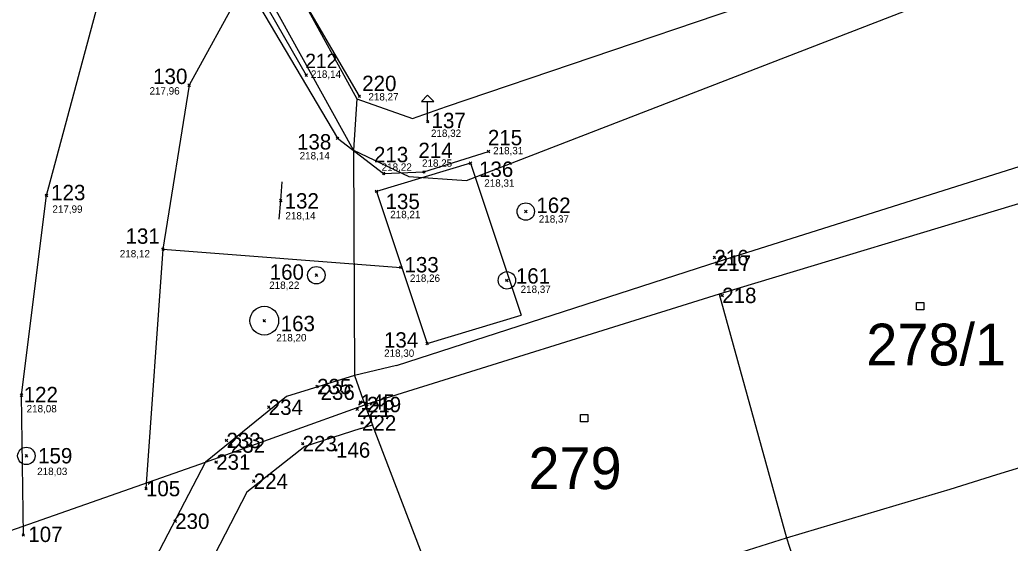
# Model space of a CAD drawing. Extents: x -711879 to -711361, y -1048782 to -1048177.
# Drawn here: x -711645.48 to -711605.14, y -1048546.23 to -1048524.94 of the extents above; entities that cross this region are included whole.
import ezdxf

# ---------------------------------------------------------------- set-up
doc = ezdxf.new("R2010")
doc.units = 0
for name, color, linetype in [('body', 7, 'Continuous'), ('kresba', 7, 'Continuous'), ('Vrstva 1', 7, 'Continuous'), ('Vrstva 15', 7, 'Continuous'), ('Vrstva 2', 7, 'Continuous'), ('Vrstva 20', 7, 'Continuous'), ('Vrstva 25', 7, 'Continuous'), ('Vrstva 41', 7, 'Continuous'), ('Vrstva 46', 7, 'Continuous'), ('výšky', 7, 'Continuous')]:
    doc.layers.add(name, color=color, linetype=linetype)

msp = doc.modelspace()

# ---------------------------------------------------------------- linework, layer by layer
at = {"layer": 'kresba'}
for p, q in [((-711636.56, -1048519.64), (-711631.65, -1048528.05)), ((-711636.32, -1048522.849), (-711633.81, -1048527.19)), ((-711636.56, -1048522.97), (-711632.54, -1048529.76)), ((-711627.12, -1048530.77), (-711630.95, -1048531.92)), ((-711627.12, -1048530.77), (-711625.06, -1048536.96)), ((-711634.85, -1048532.29), (-711634.79, -1048531.53)), ((-711630.95, -1048531.92), (-711628.89, -1048538.11)), ((-711634.91, -1048533.05), (-711634.85, -1048532.29)), ((-711639.65, -1048534.27), (-711640.34, -1048544.01)), ((-711639.65, -1048534.27), (-711629.96, -1048535.01)), ((-711628.89, -1048538.11), (-711625.06, -1048536.96))]:
    msp.add_line(p, q, dxfattribs=at)
for points in [[(-711645.33, -1048545.9), (-711645.41, -1048540.21), (-711644.39, -1048532.08), (-711642.22, -1048524), (-711639.471, -1048515.651)], [(-711636.47, -1048523.76), (-711638.58, -1048527.6), (-711639.65, -1048534.27)], [(-711628.87, -1048529.08), (-711628.87, -1048528.26), (-711628.62, -1048528.26), (-711628.87, -1048528.01), (-711629.12, -1048528.26), (-711628.87, -1048528.26)], [(-711632.54, -1048529.76), (-711630.66, -1048531.19), (-711629.02, -1048531.13), (-711626.39, -1048530.29)]]:
    msp.add_lwpolyline(points, dxfattribs=at)
for centre, radius in [((-711624.87, -1048532.74), 0.355), ((-711633.4, -1048535.33), 0.355), ((-711625.64, -1048535.54), 0.355), ((-711635.52, -1048537.18), 0.585), ((-711645.21, -1048542.68), 0.355)]:
    msp.add_circle(centre, radius, dxfattribs=at)
at = {"layer": 'Vrstva 1'}
for p, q in [((-711636.32, -1048519.83), (-711631.75, -1048528.15)), ((-711628.1, -1048528.47), (-711616.23, -1048524.45)), ((-711631.75, -1048528.15), (-711631.89, -1048530.24)), ((-711631.75, -1048528.15), (-711629.48, -1048528.95)), ((-711629.48, -1048528.95), (-711628.1, -1048528.47)), ((-711631.89, -1048530.24), (-711631.85, -1048539.41)), ((-711603.68, -1048532.09), (-711617, -1048536.1)), ((-711617, -1048536.1), (-711631.42, -1048540.6)), ((-711617, -1048536.1), (-711614.25, -1048546.01)), ((-711631.85, -1048539.41), (-711631.42, -1048540.6)), ((-711637.91, -1048542.94), (-711631.42, -1048540.6)), ((-711631.42, -1048540.6), (-711631.11, -1048541.42)), ((-711631.59, -1048541.57), (-711631.11, -1048541.42)), ((-711627.66, -1048550.43), (-711631.11, -1048541.42)), ((-711631.59, -1048541.57), (-711633.87, -1048542.3)), ((-711633.87, -1048542.3), (-711636.23, -1048544.16)), ((-711654.39, -1048548.7), (-711637.91, -1048542.94)), ((-711640.49, -1048547.86), (-711637.91, -1048542.94)), ((-711636.23, -1048544.16), (-711638.53, -1048548.61)), ((-711614.25, -1048546.01), (-711612.88, -1048550.24))]:
    msp.add_line(p, q, dxfattribs=at)
at = {"layer": 'Vrstva 2'}
for p, q in [((-711631.89, -1048530.24), (-711638.01, -1048519.17)), ((-711627.29, -1048531.47), (-711607.17, -1048523.7)), ((-711631.89, -1048530.24), (-711629.63, -1048531.31)), ((-711617.42, -1048534.9), (-711604.16, -1048530.71)), ((-711629.63, -1048531.31), (-711627.29, -1048531.47)), ((-711630.14, -1048539), (-711617.42, -1048534.9)), ((-711630.14, -1048539), (-711631.85, -1048539.41)), ((-711631.85, -1048539.41), (-711634.61, -1048540.27)), ((-711634.61, -1048540.27), (-711637.91, -1048542.94)), ((-711605.68, -1048543.44), (-711600.91, -1048541.96)), ((-711607.59, -1048544.03), (-711605.68, -1048543.44)), ((-711609.79, -1048544.68), (-711607.59, -1048544.03)), ((-711614.25, -1048546.01), (-711609.79, -1048544.68)), ((-711617.6, -1048547.07), (-711614.25, -1048546.01))]:
    msp.add_line(p, q, dxfattribs=at)
at = {"layer": 'Vrstva 20'}
for p, q in [((-711633.81, -1048527.19), (-711633.86, -1048527.14)), ((-711633.81, -1048527.19), (-711633.86, -1048527.24)), ((-711633.81, -1048527.19), (-711633.76, -1048527.14)), ((-711633.81, -1048527.19), (-711633.76, -1048527.24)), ((-711638.58, -1048527.6), (-711638.63, -1048527.55)), ((-711638.58, -1048527.6), (-711638.63, -1048527.65)), ((-711638.58, -1048527.6), (-711638.53, -1048527.55)), ((-711638.58, -1048527.6), (-711638.53, -1048527.65)), ((-711631.65, -1048528.05), (-711631.7, -1048528)), ((-711631.65, -1048528.05), (-711631.7, -1048528.1)), ((-711631.65, -1048528.05), (-711631.6, -1048528)), ((-711631.65, -1048528.05), (-711631.6, -1048528.1)), ((-711628.87, -1048529.08), (-711628.92, -1048529.03)), ((-711628.87, -1048529.08), (-711628.92, -1048529.13)), ((-711628.87, -1048529.08), (-711628.82, -1048529.03)), ((-711628.87, -1048529.08), (-711628.82, -1048529.13)), ((-711632.54, -1048529.76), (-711632.59, -1048529.71)), ((-711632.54, -1048529.76), (-711632.59, -1048529.81)), ((-711632.54, -1048529.76), (-711632.49, -1048529.71)), ((-711632.54, -1048529.76), (-711632.49, -1048529.81)), ((-711626.39, -1048530.29), (-711626.44, -1048530.24)), ((-711626.39, -1048530.29), (-711626.44, -1048530.34)), ((-711626.39, -1048530.29), (-711626.34, -1048530.24)), ((-711626.39, -1048530.29), (-711626.34, -1048530.34)), ((-711627.12, -1048530.77), (-711627.17, -1048530.72)), ((-711627.12, -1048530.77), (-711627.17, -1048530.82)), ((-711627.12, -1048530.77), (-711627.07, -1048530.72)), ((-711627.12, -1048530.77), (-711627.07, -1048530.82)), ((-711630.66, -1048531.19), (-711630.71, -1048531.14)), ((-711630.66, -1048531.19), (-711630.71, -1048531.24)), ((-711630.66, -1048531.19), (-711630.61, -1048531.14)), ((-711630.66, -1048531.19), (-711630.61, -1048531.24)), ((-711629.02, -1048531.13), (-711629.07, -1048531.08)), ((-711629.02, -1048531.13), (-711629.07, -1048531.18)), ((-711629.02, -1048531.13), (-711628.97, -1048531.08)), ((-711629.02, -1048531.13), (-711628.97, -1048531.18)), ((-711644.39, -1048532.08), (-711644.44, -1048532.03)), ((-711644.39, -1048532.08), (-711644.44, -1048532.13)), ((-711644.39, -1048532.08), (-711644.34, -1048532.03)), ((-711644.39, -1048532.08), (-711644.34, -1048532.13)), ((-711634.85, -1048532.29), (-711634.9, -1048532.24)), ((-711634.85, -1048532.29), (-711634.8, -1048532.24)), ((-711630.95, -1048531.92), (-711631, -1048531.87)), ((-711630.95, -1048531.92), (-711631, -1048531.97)), ((-711630.95, -1048531.92), (-711630.9, -1048531.87)), ((-711630.95, -1048531.92), (-711630.9, -1048531.97)), ((-711634.85, -1048532.29), (-711634.9, -1048532.34)), ((-711634.85, -1048532.29), (-711634.8, -1048532.34)), ((-711624.87, -1048532.74), (-711624.92, -1048532.69)), ((-711624.87, -1048532.74), (-711624.92, -1048532.79)), ((-711624.87, -1048532.74), (-711624.82, -1048532.69)), ((-711624.87, -1048532.74), (-711624.82, -1048532.79)), ((-711639.65, -1048534.27), (-711639.7, -1048534.22)), ((-711639.65, -1048534.27), (-711639.6, -1048534.22)), ((-711639.65, -1048534.27), (-711639.7, -1048534.32)), ((-711639.65, -1048534.27), (-711639.6, -1048534.32)), ((-711617.19, -1048534.61), (-711617.24, -1048534.56)), ((-711617.19, -1048534.61), (-711617.24, -1048534.66)), ((-711617.19, -1048534.61), (-711617.14, -1048534.56)), ((-711617.19, -1048534.61), (-711617.14, -1048534.66)), ((-711629.96, -1048535.01), (-711630.01, -1048534.96)), ((-711629.96, -1048535.01), (-711630.01, -1048535.06)), ((-711629.96, -1048535.01), (-711629.91, -1048534.96)), ((-711629.96, -1048535.01), (-711629.91, -1048535.06)), ((-711617.09, -1048534.84), (-711617.14, -1048534.79)), ((-711617.09, -1048534.84), (-711617.14, -1048534.89)), ((-711617.09, -1048534.84), (-711617.04, -1048534.79)), ((-711617.09, -1048534.84), (-711617.04, -1048534.89)), ((-711633.4, -1048535.33), (-711633.45, -1048535.28)), ((-711633.4, -1048535.33), (-711633.45, -1048535.28)), ((-711633.4, -1048535.33), (-711633.45, -1048535.38)), ((-711633.4, -1048535.33), (-711633.45, -1048535.38)), ((-711633.4, -1048535.33), (-711633.35, -1048535.28)), ((-711633.4, -1048535.33), (-711633.35, -1048535.28)), ((-711633.4, -1048535.33), (-711633.35, -1048535.38)), ((-711633.4, -1048535.33), (-711633.35, -1048535.38)), ((-711625.64, -1048535.54), (-711625.69, -1048535.49)), ((-711625.64, -1048535.54), (-711625.69, -1048535.59)), ((-711625.64, -1048535.54), (-711625.59, -1048535.49)), ((-711625.64, -1048535.54), (-711625.59, -1048535.59)), ((-711616.87, -1048536.15), (-711616.92, -1048536.1)), ((-711616.87, -1048536.15), (-711616.92, -1048536.2)), ((-711616.87, -1048536.15), (-711616.82, -1048536.1)), ((-711616.87, -1048536.15), (-711616.82, -1048536.2)), ((-711635.52, -1048537.18), (-711635.57, -1048537.13)), ((-711635.52, -1048537.18), (-711635.57, -1048537.23)), ((-711635.52, -1048537.18), (-711635.47, -1048537.13)), ((-711635.52, -1048537.18), (-711635.47, -1048537.23)), ((-711628.89, -1048538.11), (-711628.94, -1048538.06)), ((-711628.89, -1048538.11), (-711628.94, -1048538.16)), ((-711628.89, -1048538.11), (-711628.84, -1048538.06)), ((-711628.89, -1048538.11), (-711628.84, -1048538.16)), ((-711633.37, -1048539.86), (-711633.42, -1048539.81)), ((-711633.37, -1048539.86), (-711633.42, -1048539.91)), ((-711633.37, -1048539.86), (-711633.32, -1048539.81)), ((-711633.37, -1048539.86), (-711633.32, -1048539.91)), ((-711645.41, -1048540.21), (-711645.46, -1048540.16)), ((-711645.41, -1048540.21), (-711645.46, -1048540.26)), ((-711645.41, -1048540.21), (-711645.36, -1048540.16)), ((-711645.41, -1048540.21), (-711645.36, -1048540.26)), ((-711633.23, -1048540.09), (-711633.28, -1048540.04)), ((-711633.23, -1048540.09), (-711633.28, -1048540.14)), ((-711633.23, -1048540.09), (-711633.18, -1048540.04)), ((-711633.23, -1048540.09), (-711633.18, -1048540.14)), ((-711635.34, -1048540.7), (-711635.39, -1048540.65)), ((-711635.34, -1048540.7), (-711635.39, -1048540.75)), ((-711635.34, -1048540.7), (-711635.29, -1048540.65)), ((-711635.34, -1048540.7), (-711635.29, -1048540.75)), ((-711631.6, -1048540.49), (-711631.65, -1048540.44)), ((-711631.6, -1048540.49), (-711631.65, -1048540.54)), ((-711631.6, -1048540.49), (-711631.55, -1048540.44)), ((-711631.6, -1048540.49), (-711631.55, -1048540.54)), ((-711631.34, -1048540.59), (-711631.39, -1048540.54)), ((-711631.34, -1048540.59), (-711631.39, -1048540.64)), ((-711631.34, -1048540.59), (-711631.29, -1048540.54)), ((-711631.34, -1048540.59), (-711631.29, -1048540.64)), ((-711631.74, -1048540.78), (-711631.79, -1048540.73)), ((-711631.74, -1048540.78), (-711631.79, -1048540.83)), ((-711631.74, -1048540.78), (-711631.69, -1048540.73)), ((-711631.74, -1048540.78), (-711631.69, -1048540.83)), ((-711631.54, -1048541.34), (-711631.59, -1048541.29)), ((-711631.54, -1048541.34), (-711631.59, -1048541.39)), ((-711631.54, -1048541.34), (-711631.49, -1048541.29)), ((-711631.54, -1048541.34), (-711631.49, -1048541.39)), ((-711637.06, -1048542.05), (-711637.11, -1048542)), ((-711637.06, -1048542.05), (-711637.11, -1048542.1)), ((-711637.06, -1048542.05), (-711637.01, -1048542)), ((-711637.06, -1048542.05), (-711637.01, -1048542.1)), ((-711636.88, -1048542.24), (-711636.93, -1048542.19)), ((-711636.88, -1048542.24), (-711636.93, -1048542.29)), ((-711636.88, -1048542.24), (-711636.83, -1048542.19)), ((-711636.88, -1048542.24), (-711636.83, -1048542.29)), ((-711633.96, -1048542.18), (-711634.01, -1048542.13)), ((-711633.96, -1048542.18), (-711634.01, -1048542.23)), ((-711633.96, -1048542.18), (-711633.91, -1048542.13)), ((-711633.96, -1048542.18), (-711633.91, -1048542.23)), ((-711645.21, -1048542.68), (-711645.26, -1048542.63)), ((-711645.21, -1048542.68), (-711645.26, -1048542.73)), ((-711645.21, -1048542.68), (-711645.16, -1048542.63)), ((-711645.21, -1048542.68), (-711645.16, -1048542.73)), ((-711632.6, -1048542.44), (-711632.65, -1048542.39)), ((-711632.6, -1048542.44), (-711632.65, -1048542.49)), ((-711632.6, -1048542.44), (-711632.55, -1048542.39)), ((-711632.6, -1048542.44), (-711632.55, -1048542.49)), ((-711637.48, -1048542.93), (-711637.53, -1048542.88)), ((-711637.48, -1048542.93), (-711637.53, -1048542.98)), ((-711637.48, -1048542.93), (-711637.43, -1048542.88)), ((-711637.48, -1048542.93), (-711637.43, -1048542.98)), ((-711635.95, -1048543.71), (-711636, -1048543.66)), ((-711635.95, -1048543.71), (-711636, -1048543.76)), ((-711635.95, -1048543.71), (-711635.9, -1048543.66)), ((-711635.95, -1048543.71), (-711635.9, -1048543.76)), ((-711640.34, -1048544.01), (-711640.39, -1048543.96)), ((-711640.34, -1048544.01), (-711640.39, -1048544.06)), ((-711640.34, -1048544.01), (-711640.29, -1048543.96)), ((-711640.34, -1048544.01), (-711640.29, -1048544.06)), ((-711639.15, -1048545.34), (-711639.2, -1048545.29)), ((-711639.15, -1048545.34), (-711639.2, -1048545.39)), ((-711639.15, -1048545.34), (-711639.1, -1048545.29)), ((-711639.15, -1048545.34), (-711639.1, -1048545.39)), ((-711645.33, -1048545.9), (-711645.38, -1048545.85)), ((-711645.33, -1048545.9), (-711645.38, -1048545.95)), ((-711645.33, -1048545.9), (-711645.28, -1048545.85)), ((-711645.33, -1048545.9), (-711645.28, -1048545.95))]:
    msp.add_line(p, q, dxfattribs=at)
at = {"layer": 'Vrstva 25'}
for p, q in [((-711608.96, -1048536.44), (-711608.66, -1048536.44)), ((-711608.96, -1048536.74), (-711608.96, -1048536.44)), ((-711608.66, -1048536.44), (-711608.66, -1048536.74)), ((-711608.66, -1048536.74), (-711608.96, -1048536.74)), ((-711622.64, -1048541), (-711622.34, -1048541)), ((-711622.64, -1048541.3), (-711622.64, -1048541)), ((-711622.34, -1048541), (-711622.34, -1048541.3)), ((-711622.34, -1048541.3), (-711622.64, -1048541.3))]:
    msp.add_line(p, q, dxfattribs=at)
at = {"layer": 'Vrstva 41'}
for p, q in [((-711633.81, -1048527.19), (-711633.81, -1048527.19)), ((-711638.58, -1048527.6), (-711638.58, -1048527.6)), ((-711631.65, -1048528.05), (-711631.65, -1048528.05)), ((-711628.87, -1048529.08), (-711628.87, -1048529.08)), ((-711632.54, -1048529.76), (-711632.54, -1048529.76)), ((-711626.39, -1048530.29), (-711626.39, -1048530.29)), ((-711627.12, -1048530.77), (-711627.12, -1048530.77)), ((-711630.66, -1048531.19), (-711630.66, -1048531.19)), ((-711629.02, -1048531.13), (-711629.02, -1048531.13)), ((-711644.39, -1048532.08), (-711644.39, -1048532.08)), ((-711630.95, -1048531.92), (-711630.95, -1048531.92)), ((-711634.85, -1048532.29), (-711634.85, -1048532.29)), ((-711624.87, -1048532.74), (-711624.87, -1048532.74)), ((-711639.65, -1048534.27), (-711639.65, -1048534.27)), ((-711617.19, -1048534.61), (-711617.19, -1048534.61)), ((-711629.96, -1048535.01), (-711629.96, -1048535.01)), ((-711617.09, -1048534.84), (-711617.09, -1048534.84)), ((-711633.4, -1048535.33), (-711633.4, -1048535.33)), ((-711633.4, -1048535.33), (-711633.4, -1048535.33)), ((-711625.64, -1048535.54), (-711625.64, -1048535.54)), ((-711616.87, -1048536.15), (-711616.87, -1048536.15)), ((-711635.52, -1048537.18), (-711635.52, -1048537.18)), ((-711628.89, -1048538.11), (-711628.89, -1048538.11)), ((-711633.37, -1048539.86), (-711633.37, -1048539.86)), ((-711645.41, -1048540.21), (-711645.41, -1048540.21)), ((-711633.23, -1048540.09), (-711633.23, -1048540.09)), ((-711635.34, -1048540.7), (-711635.34, -1048540.7)), ((-711631.6, -1048540.49), (-711631.6, -1048540.49)), ((-711631.34, -1048540.59), (-711631.34, -1048540.59)), ((-711631.74, -1048540.78), (-711631.74, -1048540.78)), ((-711631.54, -1048541.34), (-711631.54, -1048541.34)), ((-711637.06, -1048542.05), (-711637.06, -1048542.05)), ((-711636.88, -1048542.24), (-711636.88, -1048542.24)), ((-711633.96, -1048542.18), (-711633.96, -1048542.18)), ((-711645.21, -1048542.68), (-711645.21, -1048542.68)), ((-711632.6, -1048542.44), (-711632.6, -1048542.44)), ((-711637.48, -1048542.93), (-711637.48, -1048542.93)), ((-711635.95, -1048543.71), (-711635.95, -1048543.71)), ((-711640.34, -1048544.01), (-711640.34, -1048544.01)), ((-711639.15, -1048545.34), (-711639.15, -1048545.34)), ((-711645.33, -1048545.9), (-711645.33, -1048545.9))]:
    msp.add_line(p, q, dxfattribs=at)
at = {"layer": 'Vrstva 46'}
for p, q in [((-711631.75, -1048528.15), (-711631.75, -1048528.15)), ((-711629.48, -1048528.95), (-711629.48, -1048528.95)), ((-711631.85, -1048539.41), (-711631.85, -1048539.41)), ((-711634.61, -1048540.27), (-711634.61, -1048540.27)), ((-711631.42, -1048540.6), (-711631.42, -1048540.6)), ((-711631.59, -1048541.57), (-711631.59, -1048541.57))]:
    msp.add_line(p, q, dxfattribs=at)

# ---------------------------------------------------------------- texts
at = {"layer": 'body'}
for s, height, p in [('212', 0.5832, (-711633.85, -1048526.903)), ('130', 0.625, (-711640.047, -1048527.551)), ('220', 0.625, (-711631.533, -1048527.838)), ('137', 0.625, (-711628.707, -1048529.347)), ('215', 0.625, (-711626.413, -1048530.044)), ('138', 0.625, (-711634.187, -1048530.216)), ('213', 0.625, (-711631.054, -1048530.734)), ('214', 0.625, (-711629.244, -1048530.564)), ('136', 0.625, (-711626.775, -1048531.329)), ('123', 0.625, (-711644.201, -1048532.278)), ('132', 0.625, (-711634.692, -1048532.617)), ('135', 0.625, (-711630.58, -1048532.64)), ('162', 0.625, (-711624.439, -1048532.796)), ('131', 0.625, (-711641.171, -1048534.051)), ('133', 0.625, (-711629.81, -1048535.215)), ('216', 0.625, (-711617.19, -1048534.922)), ('217', 0.625, (-711617.09, -1048535.152)), ('160', 0.625, (-711635.3, -1048535.513)), ('161', 0.625, (-711625.274, -1048535.671)), ('218', 0.625, (-711616.87, -1048536.463)), ('163', 0.625, (-711634.852, -1048537.607)), ('134', 0.625, (-711630.647, -1048538.275)), ('122', 0.625, (-711645.32, -1048540.497)), ('235', 0.625, (-711633.37, -1048540.172)), ('236', 0.625, (-711633.23, -1048540.402)), ('145', 0.625, (-711631.6, -1048540.802)), ('219', 0.625, (-711631.34, -1048540.902)), ('234', 0.625, (-711635.34, -1048541.013)), ('221', 0.625, (-711631.74, -1048541.093)), ('222', 0.625, (-711631.54, -1048541.652)), ('233', 0.625, (-711637.06, -1048542.363)), ('232', 0.625, (-711636.88, -1048542.552)), ('223', 0.625, (-711633.96, -1048542.493)), ('146', 0.625, (-711632.6, -1048542.753)), ('159', 0.625, (-711644.733, -1048542.986)), ('231', 0.625, (-711637.48, -1048543.243)), ('224', 0.625, (-711635.95, -1048544.023)), ('105', 0.625, (-711640.34, -1048544.323)), ('230', 0.625, (-711639.15, -1048545.652)), ('107', 0.625, (-711645.132, -1048546.184))]:
    msp.add_text(s, height=height, dxfattribs=at).set_placement(p)
at = {"layer": 'Vrstva 15'}
for s, p in [('278/1', (-711611, -1048539)), ('279', (-711624.76, -1048544.03))]:
    msp.add_text(s, height=1.7, dxfattribs=at).set_placement(p)
at = {"layer": 'výšky'}
for s, p in [('218,14', (-711633.62, -1048527.3)), ('217,96', (-711640.194, -1048527.98)), ('218,27', (-711631.28, -1048528.22)), ('218,32', (-711628.731, -1048529.703)), ('218,31', (-711626.2, -1048530.41)), ('218,14', (-711634.08, -1048530.62)), ('218,25', (-711629.096, -1048530.917)), ('218,22', (-711630.74, -1048531.08)), ('218,31', (-711626.56, -1048531.73)), ('217,99', (-711644.15, -1048532.79)), ('218,14', (-711634.66, -1048533.06)), ('218,21', (-711630.39, -1048533.01)), ('218,37', (-711624.34, -1048533.19)), ('218,12', (-711641.405, -1048534.604)), ('218,26', (-711629.59, -1048535.6)), ('218,22', (-711635.32, -1048535.887)), ('218,37', (-711625.08, -1048536.05)), ('218,20', (-711635.03, -1048538.02)), ('218,30', (-711630.64, -1048538.65)), ('218,08', (-711645.2, -1048540.91)), ('218,03', (-711644.77, -1048543.46))]:
    msp.add_text(s, height=0.3, dxfattribs=at).set_placement(p)

doc.saveas('drawing.dxf')
